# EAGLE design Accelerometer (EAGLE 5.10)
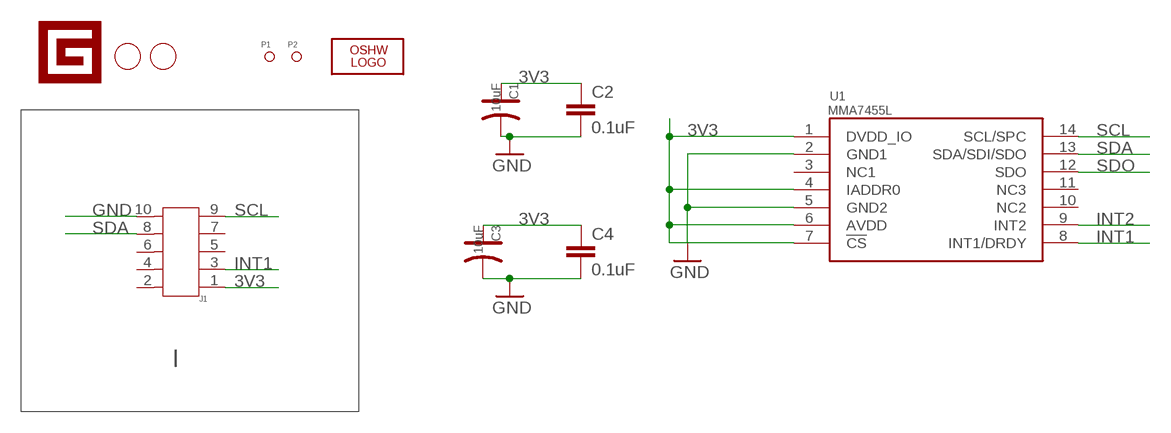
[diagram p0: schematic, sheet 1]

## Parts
C1  10uF  CAP-AVX-A  [AVX-A]
C2  0.1uF  CAPC805  [C805]
C3  10uF  CAP-AVX-A  [AVX-A]
C4  0.1uF  CAPC805  [C805]
J1  HEADER-SHF-105-01-L-D-SM  [SHF-105-01-L-D-SM]
LOGO1  LOGO-OSHW-FILLX0150-NT  [OSHW_FILLX150_NOTEXT]
P1  PAD-MARK  [ROUND-MARK-0.635]
P2  PAD-MARK  [ROUND-MARK-0.635]
U1  MMA7455L  [LGA-14]
U$1  LOGO-GADGETEER-NORMAL  [GADGETEER-SILK]
U$3  PAD-HOLE'3.2/7.0'  [HOLE-D-3.2/7.0]
U$4  PAD-HOLE'3.2/7.0'  [HOLE-D-3.2/7.0]

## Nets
3V3: C1.+ C2.1 C3.+ C4.1 J1.1 U1.1(DVDD_IO) U1.4(IADDR0) U1.6(AVDD) U1.7(!CS)
GND: C1.- C2.2 C3.- C4.2 J1.10 U1.2(GND1) U1.5(GND2)
INT1: J1.3 U1.8(INT1/DRDY)
INT2: U1.9(INT2)
SCL: J1.9 U1.14(SCL/SPC)
SDA: J1.8 U1.13(SDA/SDI/SDO)
SDO: U1.12(SDO)
Unconnected: J1.2 J1.4 J1.5 J1.6 J1.7 U1.3(NC1) U1.10(NC2) U1.11(NC3)

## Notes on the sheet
- I

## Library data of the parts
C1 C3 = Discrete:CAP*: Electrolytic Capacitors,Tantalum Capacitors and Super Capacitors
C2 C4 = dp_devices:CAP
J1 = Connector:HEADER-SHF-105-01-L-D-SM
LOGO1 = Logo:LOGO-OSHW-FILL
P1 P2 = Discreter:PAD-MARK
U1 = jer_eagle:MMA7455L
U$1 = Logo:LOGO-GADGETEER
U$3 U$4 = Discreter:PAD-HOLE

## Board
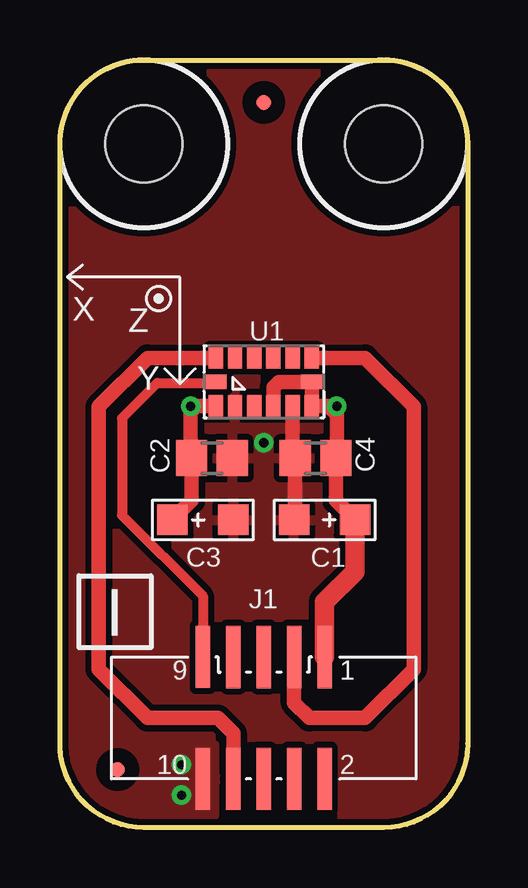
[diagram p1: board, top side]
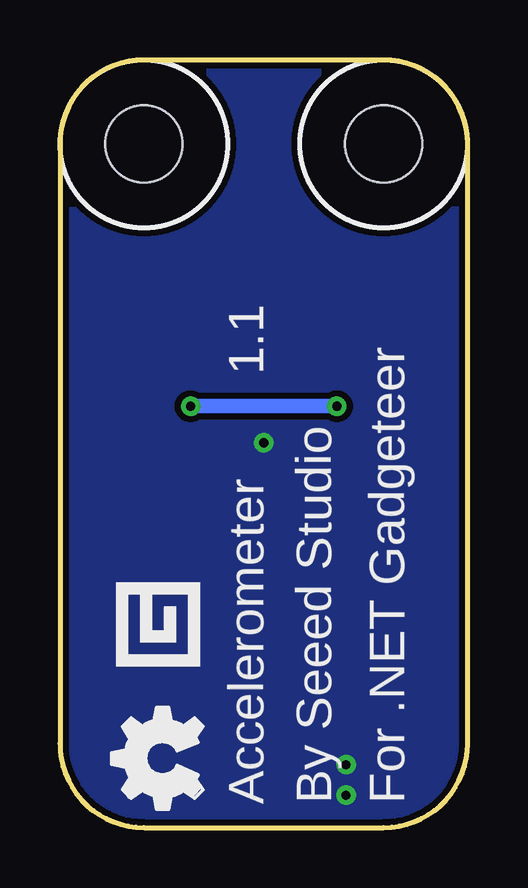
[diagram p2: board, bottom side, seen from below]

Size 17 x 32 mm. Coordinates in mm from the lower left corner, seen from the top.
Outline: 13.5,32 arc-90 17,28.5 17,3.5 arc-90 13.5,0 3.5,0 arc-90 0,3.5 0,28.5 arc-90 3.5,32 13.5,32
Copper layers (1*16): Top 0.035mm / dielectric 1.5mm / Bottom 0.035mm
Design rules "default *": minimum track width 10mil, minimum drill 8mil, track to track 6mil, track to pad 6mil, pad to pad 6mil, via to via 6mil, smd to smd 6mil, copper to edge 10mil, drill to drill 8mil, minimum pad ring 10mil, minimum via ring 8mil, stop-mask expansion 4mil, vias tented up to drill 25mil, thermal gap 10mil

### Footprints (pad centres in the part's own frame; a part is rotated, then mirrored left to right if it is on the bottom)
AVX-A = smd 1.27 x 1.27: + -1.27,0; - 1.27,0
C805 = smd 1.3 x 1.5: 1 -0.85,0; 2 0.85,0
SHF-105-01-L-D-SM = smd 0.6 x 2.6: 1 -2.54,-2.54; 2 -2.54,2.54; 3 -1.27,-2.54; 4 -1.27,2.54; 5 0,-2.54; 6 0,2.54; 7 1.27,-2.54; 8 1.27,2.54; 9 2.54,-2.546; 10 2.54,2.54
ROUND-MARK-0.635 = smd 0.635 x 0.635: P$1 0,0
LGA-14 = smd 0.6 x 0.9: 1 -2,-1; 2 -1.2,-1; 3 -0.4,-1; 4 0.4,-1; 5 1.2,-1; 6 2,-1; 8 2,1; 9 1.2,1; 10 0.4,1; 11 -0.4,1; 12 -1.2,1; 13 -2,1 | smd 0.9 x 0.6: 7 2,0; 14 -2,0
HOLE-D-3.2/7.0 = hole 3.2: 0,0

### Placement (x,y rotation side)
C1  11.04,12.82 180 top
C2  6.34,15.4 0 top
C3  5.96,12.82 0 top
C4  10.66,15.4 180 top
J1  8.5,4.57 180 top
LOGO1  11.04,0.76 90 bottom
P1  8.5,30.22 270 top
P2  2.4,2.41 0 top
U1  8.5,18.58 0 top
U$1  13.33,8.89 90 bottom
U$3  13.5,28.5 270 top
U$4  3.5,28.5 270 top

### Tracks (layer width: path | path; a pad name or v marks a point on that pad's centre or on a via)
3V3  (via drill 0.38 pad 0.81)
  Top 0.61: 10.5,18.37 U1.6 10.5,17.56 11.2,17.56 | 10.5,18.37 U1.7 10.29,18.58 | U1.4 8.9,18.34 9.13,18.58 10.29,18.58 | 5.45,17.31 v5.45,17.56 5.71,17.56 | 5.71,17.56 6.48,17.56 U1.1 | 11.55,15.82 11.51,15.79 | 5.45,17.31 5.71,17.56 | 11.2,17.56 v11.55,17.56 11.55,15.9 11.51,15.86 | 11.2,17.56 11.5,17.27 | 10.5,18.37 10.29,18.58 | C4.1 11.51,13.63 C1.+ | 5.45,17.31 5.45,15.44 C2.1 5.49,13.63 C3.+
  Top 0.813: J1.1 11.04,9.4 12.31,10.67 C1.+ | C4.1 11.51,15.86 11.55,15.82
  Bottom 0.61: 5.47,17.58 v5.45,17.56 v11.55,17.56
GND  (via drill 0.38 pad 0.81)
  Top 0.61: U1.5 9.7,16.15 | C3.- 7.3,12.89 | C4.2 9.81,12.86 C1.-
  other vias: 5.07,2.62 5.07,1.35 8.5,16.04
  pour Bottom (isolate 0.254): 17.39,32.51 17.39,-0.51 -0.39,-0.51 -0.39,32.51
  pour Top (isolate 0.254): 17.39,32.51 17.39,-0.51 -0.39,-0.51 -0.39,32.51
  pour Top (isolate 0.254, no thermals): 4.3,3.51 6.5,3.51 6.5,0.46 4.3,0.46
INT1
  Top 0.61: 9.77,7.82 J1.3 9.77,5.21 10.4,4.57 12.72,4.57 14.75,6.6 14.75,17.55 12.72,19.58 U1.8
SCL
  Top 0.406: 6.54,18.54 4.05,18.54 2.58,17.07 2.58,13.01 2.6,13.01 5.96,9.65 J1.9 | 6.54,18.54 6.59,18.54 | 6.54,18.54 U1.14
SDA
  Top 0.61: U1.13 3.65,19.58 1.62,17.55 1.62,6.6 3.65,4.57 6.59,4.57 7.23,3.94 J1.8

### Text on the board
tPlace: X | Z | Y | I
bPlace: 1.1 | For .NET Gadgeteer | By Seeed Studio | Accelerometer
